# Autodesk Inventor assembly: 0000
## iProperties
Shininess: 64.0
Length Units: 11269
Angle Units: 11279
Time Units: 11290
Mass Units: 11283
Length Display Precision: 3
Angle Display Precision: 2
Compacted: True
Created: 2004-02
Part Number: 0000
Document SubType Name: Assembly
Project: GDB000
Designer: Gilles Glemarec
Manufacturer: Standard
Standards Organization: Custom
Density: 0.0
Volumn: 0.0
Area: 0.0
PropertySet Name: Model Information
Control State: 0
Master: False
Checked Out: False
Observations: -
Revision Number: 00
